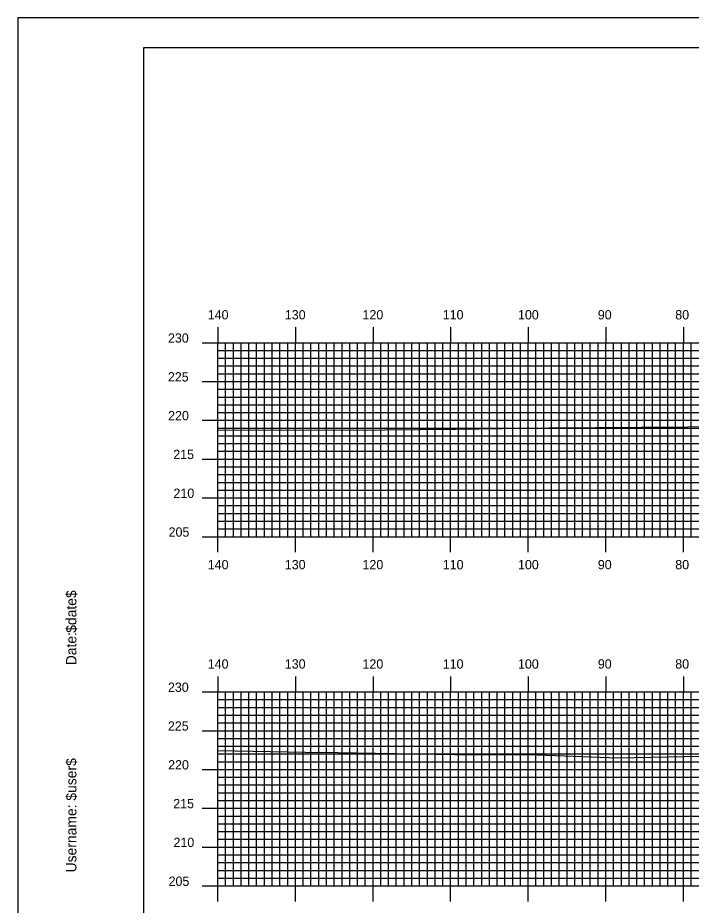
# Model space of a CAD drawing. Extents: x 1820818 to 1821161, y 442591 to 442811.
# Drawn here: x 1820817.9 to 1820904.7, y 442696.2 to 442810.5 of the extents above; entities that cross this region are included whole.
import ezdxf

# ---------------------------------------------------------------- set-up
doc = ezdxf.new("R2010")
doc.units = 0
for name, color, linetype in [('BORDER', 7, 'Continuous'), ('H_V ANNOTATION', 7, 'Continuous'), ('MAJOR', 7, 'Continuous'), ('MINOR', 7, 'Continuous'), ('PLOT BOUNDARY', 7, 'Continuous'), ('S_Roadway_Centerline', 7, 'Continuous')]:
    doc.layers.add(name, color=color, linetype=linetype)

msp = doc.modelspace()

# ---------------------------------------------------------------- linework, layer by layer
at = {"layer": 'BORDER'}
msp.add_lwpolyline([(1820834.12, 442596.67), (1821154.12, 442596.67), (1821154.12, 442806.67), (1820834.12, 442806.67)], close=True, dxfattribs=at)
at = {"layer": 'MAJOR'}
for p, q in [((1820843.72, 442770.67), (1820843.72, 442768.67)), ((1820853.72, 442770.67), (1820853.72, 442768.67)), ((1820863.72, 442770.67), (1820863.72, 442768.67)), ((1820873.72, 442770.67), (1820873.72, 442768.67)), ((1820883.72, 442770.67), (1820883.72, 442768.67)), ((1820893.72, 442770.67), (1820893.72, 442768.67)), ((1820903.72, 442770.67), (1820903.72, 442768.67)), ((1820841.71, 442768.67), (1820843.72, 442768.67)), ((1820843.72, 442768.67), (1821123.72, 442768.67)), ((1820843.72, 442743.67), (1820843.72, 442768.67)), ((1820843.72, 442743.67), (1820843.72, 442768.67)), ((1820843.72, 442768.67), (1821123.72, 442768.67)), ((1820853.72, 442743.67), (1820853.72, 442768.67)), ((1820863.72, 442743.67), (1820863.72, 442768.67)), ((1820873.72, 442743.67), (1820873.72, 442768.67)), ((1820883.72, 442743.67), (1820883.72, 442768.67)), ((1820893.72, 442743.67), (1820893.72, 442768.67)), ((1820903.72, 442743.67), (1820903.72, 442768.67)), ((1820841.71, 442763.67), (1820843.72, 442763.67)), ((1820843.72, 442763.67), (1821123.72, 442763.67)), ((1820841.71, 442758.67), (1820843.72, 442758.67)), ((1820843.72, 442758.67), (1821123.72, 442758.67)), ((1820841.71, 442753.67), (1820843.72, 442753.67)), ((1820843.72, 442753.67), (1821123.72, 442753.67)), ((1820841.71, 442748.67), (1820843.72, 442748.67)), ((1820843.72, 442748.67), (1821123.72, 442748.67)), ((1820841.71, 442743.67), (1820843.72, 442743.67)), ((1820843.72, 442743.67), (1821123.72, 442743.67)), ((1820843.72, 442743.67), (1821123.72, 442743.67)), ((1820843.72, 442741.66), (1820843.72, 442743.67)), ((1820853.72, 442741.66), (1820853.72, 442743.67)), ((1820863.72, 442741.66), (1820863.72, 442743.67)), ((1820873.72, 442741.66), (1820873.72, 442743.67)), ((1820883.72, 442741.66), (1820883.72, 442743.67)), ((1820893.72, 442741.66), (1820893.72, 442743.67)), ((1820903.72, 442741.66), (1820903.72, 442743.67)), ((1820843.72, 442725.67), (1820843.72, 442723.67)), ((1820853.72, 442725.67), (1820853.72, 442723.67)), ((1820863.72, 442725.67), (1820863.72, 442723.67)), ((1820873.72, 442725.67), (1820873.72, 442723.67)), ((1820883.72, 442725.67), (1820883.72, 442723.67)), ((1820893.72, 442725.67), (1820893.72, 442723.67)), ((1820903.72, 442725.67), (1820903.72, 442723.67)), ((1820841.71, 442723.67), (1820843.72, 442723.67)), ((1820843.72, 442723.67), (1821123.72, 442723.67)), ((1820843.72, 442698.67), (1820843.72, 442723.67)), ((1820843.72, 442698.67), (1820843.72, 442723.67)), ((1820843.72, 442723.67), (1821123.72, 442723.67)), ((1820853.72, 442698.67), (1820853.72, 442723.67)), ((1820863.72, 442698.67), (1820863.72, 442723.67)), ((1820873.72, 442698.67), (1820873.72, 442723.67)), ((1820883.72, 442698.67), (1820883.72, 442723.67)), ((1820893.72, 442698.67), (1820893.72, 442723.67)), ((1820903.72, 442698.67), (1820903.72, 442723.67)), ((1820841.71, 442718.67), (1820843.72, 442718.67)), ((1820843.72, 442718.67), (1821123.72, 442718.67)), ((1820841.71, 442713.67), (1820843.72, 442713.67)), ((1820843.72, 442713.67), (1821123.72, 442713.67)), ((1820841.71, 442708.67), (1820843.72, 442708.67)), ((1820843.72, 442708.67), (1821123.72, 442708.67)), ((1820841.71, 442703.67), (1820843.72, 442703.67)), ((1820843.72, 442703.67), (1821123.72, 442703.67)), ((1820841.71, 442698.67), (1820843.72, 442698.67)), ((1820843.72, 442698.67), (1821123.72, 442698.67)), ((1820843.72, 442698.67), (1821123.72, 442698.67)), ((1820843.72, 442696.66), (1820843.72, 442698.67)), ((1820853.72, 442696.66), (1820853.72, 442698.67)), ((1820863.72, 442696.66), (1820863.72, 442698.67)), ((1820873.72, 442696.66), (1820873.72, 442698.67)), ((1820883.72, 442696.66), (1820883.72, 442698.67)), ((1820893.72, 442696.66), (1820893.72, 442698.67)), ((1820903.72, 442696.66), (1820903.72, 442698.67))]:
    msp.add_line(p, q, dxfattribs=at)
at = {"layer": 'MINOR'}
for p, q in [((1820843.72, 442767.67), (1821123.72, 442767.67)), ((1820843.72, 442767.67), (1820845.72, 442767.67)), ((1820844.72, 442743.67), (1820844.72, 442768.67)), ((1820845.72, 442743.67), (1820845.72, 442768.67)), ((1820846.72, 442743.67), (1820846.72, 442768.67)), ((1820847.72, 442743.67), (1820847.72, 442768.67)), ((1820848.72, 442743.67), (1820848.72, 442768.67)), ((1820849.72, 442743.67), (1820849.72, 442768.67)), ((1820850.72, 442743.67), (1820850.72, 442768.67)), ((1820851.72, 442743.67), (1820851.72, 442768.67)), ((1820852.72, 442743.67), (1820852.72, 442768.67)), ((1820854.72, 442743.67), (1820854.72, 442768.67)), ((1820855.72, 442743.67), (1820855.72, 442768.67)), ((1820856.72, 442743.67), (1820856.72, 442768.67)), ((1820857.72, 442743.67), (1820857.72, 442768.67)), ((1820858.72, 442743.67), (1820858.72, 442768.67)), ((1820859.72, 442743.67), (1820859.72, 442768.67)), ((1820860.72, 442743.67), (1820860.72, 442768.67)), ((1820861.72, 442743.67), (1820861.72, 442768.67)), ((1820862.72, 442743.67), (1820862.72, 442768.67)), ((1820864.72, 442743.67), (1820864.72, 442768.67)), ((1820865.72, 442743.67), (1820865.72, 442768.67)), ((1820866.72, 442743.67), (1820866.72, 442768.67)), ((1820867.72, 442743.67), (1820867.72, 442768.67)), ((1820868.72, 442743.67), (1820868.72, 442768.67)), ((1820869.72, 442743.67), (1820869.72, 442768.67)), ((1820870.72, 442743.67), (1820870.72, 442768.67)), ((1820871.72, 442743.67), (1820871.72, 442768.67)), ((1820872.72, 442743.67), (1820872.72, 442768.67)), ((1820874.72, 442743.67), (1820874.72, 442768.67)), ((1820875.72, 442743.67), (1820875.72, 442768.67)), ((1820876.72, 442743.67), (1820876.72, 442768.67)), ((1820877.72, 442743.67), (1820877.72, 442768.67)), ((1820878.72, 442743.67), (1820878.72, 442768.67)), ((1820879.72, 442743.67), (1820879.72, 442768.67)), ((1820880.72, 442743.67), (1820880.72, 442768.67)), ((1820881.72, 442743.67), (1820881.72, 442768.67)), ((1820882.72, 442743.67), (1820882.72, 442768.67)), ((1820884.72, 442743.67), (1820884.72, 442768.67)), ((1820885.72, 442743.67), (1820885.72, 442768.67)), ((1820886.72, 442743.67), (1820886.72, 442768.67)), ((1820887.72, 442743.67), (1820887.72, 442768.67)), ((1820888.72, 442743.67), (1820888.72, 442768.67)), ((1820889.72, 442743.67), (1820889.72, 442768.67)), ((1820890.72, 442743.67), (1820890.72, 442768.67)), ((1820891.72, 442743.67), (1820891.72, 442768.67)), ((1820892.72, 442743.67), (1820892.72, 442768.67)), ((1820894.72, 442743.67), (1820894.72, 442768.67)), ((1820895.72, 442743.67), (1820895.72, 442768.67)), ((1820896.72, 442743.67), (1820896.72, 442768.67)), ((1820897.72, 442743.67), (1820897.72, 442768.67)), ((1820898.72, 442743.67), (1820898.72, 442768.67)), ((1820899.72, 442743.67), (1820899.72, 442768.67)), ((1820900.72, 442743.67), (1820900.72, 442768.67)), ((1820901.72, 442743.67), (1820901.72, 442768.67)), ((1820902.72, 442743.67), (1820902.72, 442768.67)), ((1820904.72, 442743.67), (1820904.72, 442768.67)), ((1820843.72, 442766.67), (1821123.72, 442766.67)), ((1820843.72, 442766.67), (1820845.72, 442766.67)), ((1820843.72, 442765.67), (1821123.72, 442765.67)), ((1820843.72, 442765.67), (1820845.72, 442765.67)), ((1820843.72, 442764.67), (1821123.72, 442764.67)), ((1820843.72, 442764.67), (1820845.72, 442764.67)), ((1820843.72, 442762.67), (1821123.72, 442762.67)), ((1820843.72, 442762.67), (1820845.72, 442762.67)), ((1820843.72, 442761.67), (1821123.72, 442761.67)), ((1820843.72, 442761.67), (1820845.72, 442761.67)), ((1820843.72, 442760.67), (1821123.72, 442760.67)), ((1820843.72, 442760.67), (1820845.72, 442760.67)), ((1820843.72, 442759.67), (1821123.72, 442759.67)), ((1820843.72, 442759.67), (1820845.72, 442759.67)), ((1820843.72, 442757.67), (1821123.72, 442757.67)), ((1820843.72, 442757.67), (1820845.72, 442757.67)), ((1820843.72, 442756.67), (1821123.72, 442756.67)), ((1820843.72, 442756.67), (1820845.72, 442756.67)), ((1820843.72, 442755.67), (1821123.72, 442755.67)), ((1820843.72, 442755.67), (1820845.72, 442755.67)), ((1820843.72, 442754.67), (1821123.72, 442754.67)), ((1820843.72, 442754.67), (1820845.72, 442754.67)), ((1820843.72, 442752.67), (1821123.72, 442752.67)), ((1820843.72, 442752.67), (1820845.72, 442752.67)), ((1820843.72, 442751.67), (1821123.72, 442751.67)), ((1820843.72, 442751.67), (1820845.72, 442751.67)), ((1820843.72, 442750.67), (1821123.72, 442750.67)), ((1820843.72, 442750.67), (1820845.72, 442750.67)), ((1820843.72, 442749.67), (1821123.72, 442749.67)), ((1820843.72, 442749.67), (1820845.72, 442749.67)), ((1820843.72, 442747.67), (1821123.72, 442747.67)), ((1820843.72, 442747.67), (1820845.72, 442747.67)), ((1820843.72, 442746.67), (1821123.72, 442746.67)), ((1820843.72, 442746.67), (1820845.72, 442746.67)), ((1820843.72, 442745.67), (1821123.72, 442745.67)), ((1820843.72, 442745.67), (1820845.72, 442745.67)), ((1820843.72, 442744.67), (1821123.72, 442744.67)), ((1820843.72, 442744.67), (1820845.72, 442744.67)), ((1820844.72, 442698.67), (1820844.72, 442723.67)), ((1820845.72, 442698.67), (1820845.72, 442723.67)), ((1820846.72, 442698.67), (1820846.72, 442723.67)), ((1820847.72, 442698.67), (1820847.72, 442723.67)), ((1820848.72, 442698.67), (1820848.72, 442723.67)), ((1820849.72, 442698.67), (1820849.72, 442723.67)), ((1820850.72, 442698.67), (1820850.72, 442723.67)), ((1820851.72, 442698.67), (1820851.72, 442723.67)), ((1820852.72, 442698.67), (1820852.72, 442723.67)), ((1820854.72, 442698.67), (1820854.72, 442723.67)), ((1820855.72, 442698.67), (1820855.72, 442723.67)), ((1820856.72, 442698.67), (1820856.72, 442723.67)), ((1820857.72, 442698.67), (1820857.72, 442723.67)), ((1820858.72, 442698.67), (1820858.72, 442723.67)), ((1820859.72, 442698.67), (1820859.72, 442723.67)), ((1820860.72, 442698.67), (1820860.72, 442723.67)), ((1820861.72, 442698.67), (1820861.72, 442723.67)), ((1820862.72, 442698.67), (1820862.72, 442723.67)), ((1820864.72, 442698.67), (1820864.72, 442723.67)), ((1820865.72, 442698.67), (1820865.72, 442723.67)), ((1820866.72, 442698.67), (1820866.72, 442723.67)), ((1820867.72, 442698.67), (1820867.72, 442723.67)), ((1820868.72, 442698.67), (1820868.72, 442723.67)), ((1820869.72, 442698.67), (1820869.72, 442723.67)), ((1820870.72, 442698.67), (1820870.72, 442723.67)), ((1820871.72, 442698.67), (1820871.72, 442723.67)), ((1820872.72, 442698.67), (1820872.72, 442723.67)), ((1820874.72, 442698.67), (1820874.72, 442723.67)), ((1820875.72, 442698.67), (1820875.72, 442723.67)), ((1820876.72, 442698.67), (1820876.72, 442723.67)), ((1820877.72, 442698.67), (1820877.72, 442723.67)), ((1820878.72, 442698.67), (1820878.72, 442723.67)), ((1820879.72, 442698.67), (1820879.72, 442723.67)), ((1820880.72, 442698.67), (1820880.72, 442723.67)), ((1820881.72, 442698.67), (1820881.72, 442723.67)), ((1820882.72, 442698.67), (1820882.72, 442723.67)), ((1820884.72, 442698.67), (1820884.72, 442723.67)), ((1820885.72, 442698.67), (1820885.72, 442723.67)), ((1820886.72, 442698.67), (1820886.72, 442723.67)), ((1820887.72, 442698.67), (1820887.72, 442723.67)), ((1820888.72, 442698.67), (1820888.72, 442723.67)), ((1820889.72, 442698.67), (1820889.72, 442723.67)), ((1820890.72, 442698.67), (1820890.72, 442723.67)), ((1820891.72, 442698.67), (1820891.72, 442723.67)), ((1820892.72, 442698.67), (1820892.72, 442723.67)), ((1820894.72, 442698.67), (1820894.72, 442723.67)), ((1820895.72, 442698.67), (1820895.72, 442723.67)), ((1820896.72, 442698.67), (1820896.72, 442723.67)), ((1820897.72, 442698.67), (1820897.72, 442723.67)), ((1820898.72, 442698.67), (1820898.72, 442723.67)), ((1820899.72, 442698.67), (1820899.72, 442723.67)), ((1820900.72, 442698.67), (1820900.72, 442723.67)), ((1820901.72, 442698.67), (1820901.72, 442723.67)), ((1820902.72, 442698.67), (1820902.72, 442723.67)), ((1820904.72, 442698.67), (1820904.72, 442723.67)), ((1820843.72, 442722.67), (1821123.72, 442722.67)), ((1820843.72, 442722.67), (1820845.72, 442722.67)), ((1820843.72, 442721.67), (1821123.72, 442721.67)), ((1820843.72, 442721.67), (1820845.72, 442721.67)), ((1820843.72, 442720.67), (1821123.72, 442720.67)), ((1820843.72, 442720.67), (1820845.72, 442720.67)), ((1820843.72, 442719.67), (1821123.72, 442719.67)), ((1820843.72, 442719.67), (1820845.72, 442719.67)), ((1820843.72, 442717.67), (1821123.72, 442717.67)), ((1820843.72, 442717.67), (1820845.72, 442717.67)), ((1820843.72, 442716.67), (1821123.72, 442716.67)), ((1820843.72, 442716.67), (1820845.72, 442716.67)), ((1820843.72, 442715.67), (1821123.72, 442715.67)), ((1820843.72, 442715.67), (1820845.72, 442715.67)), ((1820843.72, 442714.67), (1821123.72, 442714.67)), ((1820843.72, 442714.67), (1820845.72, 442714.67)), ((1820843.72, 442712.67), (1821123.72, 442712.67)), ((1820843.72, 442712.67), (1820845.72, 442712.67)), ((1820843.72, 442711.67), (1821123.72, 442711.67)), ((1820843.72, 442711.67), (1820845.72, 442711.67)), ((1820843.72, 442710.67), (1821123.72, 442710.67)), ((1820843.72, 442710.67), (1820845.72, 442710.67)), ((1820843.72, 442709.67), (1821123.72, 442709.67)), ((1820843.72, 442709.67), (1820845.72, 442709.67)), ((1820843.72, 442707.67), (1821123.72, 442707.67)), ((1820843.72, 442707.67), (1820845.72, 442707.67)), ((1820843.72, 442706.67), (1821123.72, 442706.67)), ((1820843.72, 442706.67), (1820845.72, 442706.67)), ((1820843.72, 442705.67), (1821123.72, 442705.67)), ((1820843.72, 442705.67), (1820845.72, 442705.67)), ((1820843.72, 442704.67), (1821123.72, 442704.67)), ((1820843.72, 442704.67), (1820845.72, 442704.67)), ((1820843.72, 442702.67), (1821123.72, 442702.67)), ((1820843.72, 442702.67), (1820845.72, 442702.67)), ((1820843.72, 442701.67), (1821123.72, 442701.67)), ((1820843.72, 442701.67), (1820845.72, 442701.67)), ((1820843.72, 442700.67), (1821123.72, 442700.67)), ((1820843.72, 442700.67), (1820845.72, 442700.67)), ((1820843.72, 442699.67), (1821123.72, 442699.67)), ((1820843.72, 442699.67), (1820845.72, 442699.67))]:
    msp.add_line(p, q, dxfattribs=at)
at = {"layer": 'PLOT BOUNDARY'}
msp.add_lwpolyline([(1820817.93, 442590.55), (1821157.93, 442590.55), (1821157.93, 442810.55), (1820817.93, 442810.55)], close=True, dxfattribs=at)
at = {"layer": 'S_Roadway_Centerline'}
for points in [[(1820843.72, 442757.45), (1820846.18, 442757.4), (1820848.12, 442757.43), (1820851.86, 442757.38), (1820865.22, 442757.44), (1820874.34, 442757.53), (1820886.36, 442757.69), (1820916.16, 442757.92), (1820930.08, 442758.08), (1820936.08, 442758.16), (1820948.48, 442758.31), (1820974.76, 442758.61), (1820988.97, 442758.52), (1821000.35, 442758.6), (1821007.84, 442758.74), (1821017.58, 442758.53)], [(1820843.72, 442716.12), (1820854.99, 442715.91), (1820859.22, 442715.84), (1820861.5, 442715.82), (1820874.2, 442715.6), (1820883.79, 442715.59), (1820895.28, 442715.19), (1820910.24, 442715.45), (1820911.6, 442715.46), (1820923.49, 442715.52), (1820928.55, 442715.48), (1820938.15, 442715.42), (1820945.92, 442715.43), (1820955.97, 442715.42), (1820977.1, 442715.26), (1820979.21, 442715.19), (1820980.17, 442715.17), (1820993.31, 442715.11), (1820996.2, 442715.11), (1821004.69, 442715.17), (1821013.58, 442715.11), (1821018.78, 442715.08)]]:
    msp.add_lwpolyline(points, dxfattribs=at)

# ---------------------------------------------------------------- texts
at = {"layer": 'BORDER'}
for s, p in [('$date$', (1820825.49, 442731.28)), ('Date:', (1820825.49, 442727.1)), ('$user$', (1820825.49, 442709.65)), ('Username:', (1820825.49, 442700.4))]:
    msp.add_text(s, height=1.339, rotation=90, dxfattribs=at).set_placement(p)
at = {"layer": 'H_V ANNOTATION'}
for s, p in [('140', (1820842.42, 442771.67)), ('130', (1820852.35, 442771.67)), ('120', (1820862.36, 442771.67)), ('110', (1820872.7, 442771.67)), ('100', (1820882.4, 442771.67)), ('90', (1820892.69, 442771.67)), ('80', (1820902.67, 442771.67)), ('230', (1820837.29, 442768.67)), ('225', (1820837.28, 442763.67)), ('220', (1820837.31, 442758.67)), ('215', (1820837.97, 442753.67)), ('210', (1820838, 442748.67)), ('205', (1820837.37, 442743.67)), ('140', (1820842.42, 442739.47)), ('130', (1820852.35, 442739.47)), ('120', (1820862.36, 442739.47)), ('110', (1820872.7, 442739.47)), ('100', (1820882.4, 442739.47)), ('90', (1820892.69, 442739.47)), ('80', (1820902.67, 442739.47)), ('140', (1820842.42, 442726.67)), ('130', (1820852.35, 442726.67)), ('120', (1820862.36, 442726.67)), ('110', (1820872.7, 442726.67)), ('100', (1820882.4, 442726.67)), ('90', (1820892.69, 442726.67)), ('80', (1820902.67, 442726.67)), ('230', (1820837.29, 442723.67)), ('225', (1820837.28, 442718.67)), ('220', (1820837.31, 442713.67)), ('215', (1820837.97, 442708.67)), ('210', (1820838, 442703.67)), ('205', (1820837.37, 442698.67))]:
    msp.add_text(s, height=1.2, dxfattribs=at).set_placement(p)
at = {"layer": 'MAJOR'}
for p in [(1820843.71, 442743.67), (1820843.71, 442698.67)]:
    msp.add_text('-', height=0.012, dxfattribs=at).set_placement(p)

doc.saveas('drawing.dxf')
